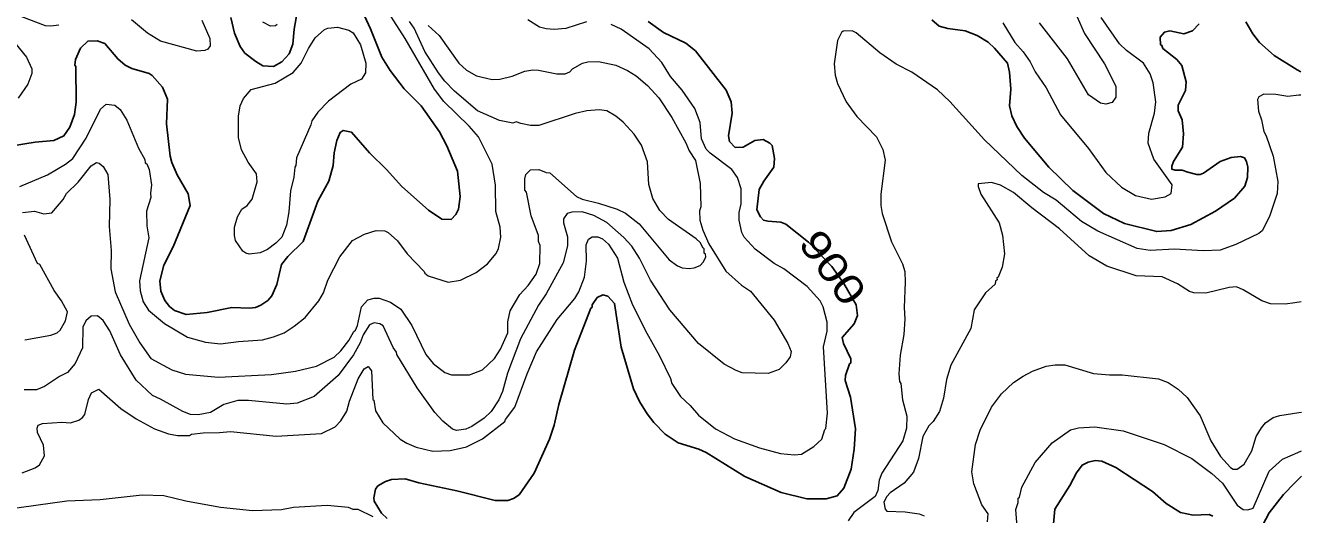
# Model space of a CAD drawing. Extents: x 447.8 to 473.9, y 7733.1 to 7760.8.
# Drawn here: x 470.364 to 473.895, y 7756.976 to 7758.328 of the extents above; entities that cross this region are included whole.
import ezdxf
from ezdxf.enums import TextEntityAlignment as Align

# ---------------------------------------------------------------- set-up
doc = ezdxf.new("R2010")
doc.units = 0
doc.header["$LTSCALE"] = 0.032
doc.layers.add('1', color=7, linetype='Continuous', lineweight=25)
doc.layers.add('2', color=7, linetype='Continuous', lineweight=13)
doc.layers.add('61', color=7, linetype='Continuous')

msp = doc.modelspace()

# ---------------------------------------------------------------- linework, layer by layer
at = {"layer": '1'}
for points in [[(471.5091, 7758.0338), (471.4587, 7758.1053), (471.4119, 7758.1529), (471.373, 7758.2035), (471.3501, 7758.2402), (471.3188, 7758.3188), (471.2785, 7758.4048)], [(471.1166, 7758.3701), (471.1071, 7758.3179), (471.1038, 7758.2762), (471.0933, 7758.2498), (471.0731, 7758.2274), (471.0504, 7758.2143), (471.0209, 7758.216), (471.0008, 7758.2279), (470.971, 7758.2515), (470.9578, 7758.2697), (470.9425, 7758.3065), (470.9321, 7758.3499)], [(472.8716, 7758.3437), (472.8917, 7758.3263), (472.9162, 7758.3198), (472.9639, 7758.3134), (472.9968, 7758.3), (473.0278, 7758.2819), (473.0455, 7758.2652), (473.0809, 7758.2235), (473.0869, 7758.1988), (473.0901, 7758.1521), (473.087, 7758.1056), (473.093, 7758.0783), (473.1068, 7758.0484), (473.1284, 7758.0164), (473.1954, 7757.9363), (473.2618, 7757.8715), (473.3469, 7757.8078), (473.4051, 7757.7802), (473.4942, 7757.758), (473.5339, 7757.7612), (473.5889, 7757.7778), (473.6567, 7757.8145), (473.7093, 7757.85), (473.7375, 7757.8833), (473.745, 7757.9071), (473.7458, 7757.9359), (473.7428, 7757.9512), (473.7367, 7757.9622), (473.7258, 7757.9655), (473.7002, 7757.963), (473.6693, 7757.9513), (473.624, 7757.9193), (473.6146, 7757.9161), (473.6048, 7757.9157), (473.5804, 7757.922), (473.5646, 7757.9279), (473.5449, 7757.9278), (473.5363, 7757.9304), (473.5355, 7757.9385), (473.5402, 7757.9512), (473.5655, 7757.9911), (473.5686, 7758.0281), (473.5646, 7758.0666), (473.5535, 7758.0918), (473.5535, 7758.1072), (473.5742, 7758.1484), (473.5759, 7758.1716), (473.5636, 7758.2175), (473.55, 7758.2335), (473.5107, 7758.2644), (473.5084, 7758.2725), (473.5047, 7758.2744), (473.5039, 7758.2952), (473.5152, 7758.3095), (473.5302, 7758.3127), (473.5691, 7758.3047), (473.5934, 7758.3128), (473.6115, 7758.3326)], [(472.4064, 7757.7898), (472.3976, 7757.7982), (472.3879, 7757.8178), (472.3944, 7757.8739), (472.4068, 7757.8975), (472.4345, 7757.9358), (472.436, 7757.9603), (472.4297, 7757.9962), (472.4237, 7758.0026), (472.4051, 7758.0128), (472.3824, 7758.0097), (472.35, 7757.9911), (472.3274, 7757.9905), (472.3119, 7758.0066), (472.3087, 7758.0222), (472.319, 7758.085), (472.3169, 7758.1169), (472.3029, 7758.1491), (472.2175, 7758.258), (472.1911, 7758.279), (472.1295, 7758.3079), (472.0865, 7758.3391)], [(473.7406, 7758.3376), (473.76, 7758.305), (473.7782, 7758.281), (473.8189, 7758.2449), (473.883, 7758.2054), (473.893, 7758.1992)], [(470.2923, 7757.9896), (470.3908, 7758.0049), (470.4425, 7758.0097), (470.4702, 7758.0224), (470.486, 7758.0469), (470.4994, 7758.0819), (470.5042, 7758.1156), (470.5026, 7758.2145), (470.5003, 7758.2177), (470.5022, 7758.2339), (470.5155, 7758.2654), (470.5364, 7758.2845), (470.5619, 7758.2854), (470.5832, 7758.2775), (470.6188, 7758.2352), (470.6393, 7758.2182), (470.6579, 7758.2088), (470.7057, 7758.1947), (470.7145, 7758.1897), (470.7431, 7758.1572), (470.7565, 7758.1242), (470.7536, 7758.0559), (470.7642, 7757.9666), (470.7685, 7757.949), (470.7833, 7757.9148), (470.8136, 7757.8622), (470.8191, 7757.8299), (470.7726, 7757.716), (470.7465, 7757.6648), (470.7352, 7757.6215), (470.7386, 7757.5931), (470.7492, 7757.5672), (470.7618, 7757.5503), (470.7759, 7757.5396), (470.808, 7757.5288), (470.8662, 7757.5343), (470.9347, 7757.5479), (470.9839, 7757.5456), (471, 7757.5481), (471.0149, 7757.5541), (471.0342, 7757.5675), (471.0453, 7757.5801), (471.0588, 7757.6118), (471.0722, 7757.6665), (471.0897, 7757.6885), (471.1318, 7757.7308), (471.1724, 7757.8422), (471.2031, 7757.8968), (471.2152, 7757.9408), (471.2176, 7757.976), (471.2252, 7758.0099), (471.2348, 7758.0321), (471.2429, 7758.0377), (471.2659, 7758.0326), (471.3154, 7757.9752), (471.3625, 7757.9298), (471.405, 7757.8824), (471.4792, 7757.8171), (471.5156, 7757.7918), (471.542, 7757.7913), (471.5547, 7757.8053)], [(471.5547, 7757.8053), (471.562, 7757.8198), (471.5663, 7757.8546), (471.559, 7757.9251), (471.5296, 7757.9949), (471.5091, 7758.0338)], [(472.5954, 7757.6613), (472.5307, 7757.7282), (472.4681, 7757.778), (472.4537, 7757.7836), (472.4182, 7757.7862), (472.4064, 7757.7898)], [(471.3648, 7756.9641), (471.3489, 7756.9792), (471.3285, 7757.012), (471.3276, 7757.022), (471.3324, 7757.0457), (471.3388, 7757.055), (471.3596, 7757.0663), (471.3767, 7757.0719), (471.4148, 7757.0742), (471.4525, 7757.0629), (471.5572, 7757.0414), (471.6637, 7757.0141), (471.6983, 7757.0141), (471.7141, 7757.0199), (471.7295, 7757.0298), (471.7717, 7757.0898), (471.814, 7757.1841), (471.8269, 7757.2229), (471.8396, 7757.2799), (471.8832, 7757.4301), (471.9286, 7757.546), (471.9317, 7757.5484), (471.9315, 7757.5552), (471.9458, 7757.5753), (471.9616, 7757.5825), (471.9755, 7757.5796), (471.9937, 7757.5594), (472.0119, 7757.4381), (472.0466, 7757.3232), (472.0627, 7757.2879), (472.0837, 7757.2537), (472.1021, 7757.2299), (472.1341, 7757.1975), (472.1696, 7757.1738), (472.2269, 7757.1563), (472.2473, 7757.1474), (472.3541, 7757.0808), (472.455, 7757.0359), (472.5262, 7757.0189), (472.5791, 7757.019), (472.6101, 7757.0267), (472.6284, 7757.0479), (472.6485, 7757.1011), (472.6572, 7757.1565), (472.6605, 7757.2126), (472.647, 7757.3004), (472.6317, 7757.3463), (472.6329, 7757.3596), (472.6443, 7757.3921), (472.6476, 7757.3945), (472.6476, 7757.4058), (472.6274, 7757.4488), (472.6238, 7757.4649), (472.657, 7757.5029), (472.666, 7757.5261), (472.6622, 7757.5549), (472.6286, 7757.6144), (472.5954, 7757.6613)], [(473.6491, 7756.9711), (473.6397, 7756.9756), (473.5953, 7756.9734), (473.5599, 7756.9812), (473.5205, 7757.0056), (473.4825, 7757.039), (473.381, 7757.1057), (473.3423, 7757.1226), (473.3242, 7757.1247), (473.3046, 7757.1198), (473.2875, 7757.1119), (473.272, 7757.0908), (473.2538, 7757.0561), (473.2119, 7756.9898), (473.2089, 7756.9497)], [(473.8947, 7757.0816), (473.8766, 7757.0631), (473.845, 7757.0307), (473.8051, 7756.9804), (473.7684, 7756.9103)]]:
    msp.add_lwpolyline(points, dxfattribs=at)
at = {"layer": '2'}
msp.add_line((473.8878, 7757.2579), (473.8944, 7757.2589), dxfattribs=at)
for points in [[(471.3017, 7757.7511), (471.3343, 7757.7611), (471.3577, 7757.7595), (471.3677, 7757.7554), (471.393, 7757.7318), (471.4197, 7757.696), (471.4665, 7757.6478), (471.4684, 7757.643), (471.4784, 7757.6356), (471.5332, 7757.6178), (471.5671, 7757.6233), (471.611, 7757.6443), (471.6419, 7757.6685), (471.6659, 7757.6974), (471.6729, 7757.7115), (471.6793, 7757.742), (471.677, 7757.7705), (471.665, 7757.8138), (471.6641, 7757.8862), (471.6553, 7757.9439), (471.6171, 7758.02), (471.5917, 7758.0492), (471.5218, 7758.1179), (471.4955, 7758.1518), (471.4147, 7758.2921), (471.3431, 7758.4033)], [(470.4558, 7758.3287), (470.4341, 7758.3256), (470.419, 7758.3272), (470.3532, 7758.3515)], [(470.8519, 7758.3425), (470.8742, 7758.2913), (470.8744, 7758.2711), (470.8681, 7758.2625), (470.8601, 7758.2583), (470.8378, 7758.2566), (470.7374, 7758.2844), (470.7016, 7758.3067), (470.6568, 7758.3438)], [(471.9159, 7758.3382), (471.8594, 7758.3197), (471.8265, 7758.3168), (471.8041, 7758.3184), (471.7865, 7758.3231), (471.7536, 7758.3432)], [(473.0679, 7758.3349), (473.1015, 7758.2804), (473.1244, 7758.2545), (473.1435, 7758.2271), (473.158, 7758.1997), (473.1883, 7758.155), (473.2278, 7758.0805), (473.3055, 7757.9875), (473.3533, 7757.9213), (473.3965, 7757.8811), (473.4353, 7757.8573), (473.4794, 7757.8478), (473.5178, 7757.8539), (473.5341, 7757.8633), (473.5373, 7757.8869), (473.4865, 7757.9578), (473.4703, 7758.0026), (473.4722, 7758.0302), (473.4877, 7758.0854), (473.4917, 7758.1168), (473.4844, 7758.1691), (473.4759, 7758.1937), (473.4577, 7758.2231), (473.4102, 7758.2587), (473.3913, 7758.2769), (473.3407, 7758.3502)], [(473.2727, 7758.3534), (473.2942, 7758.3053), (473.3492, 7758.2218), (473.3811, 7758.1596), (473.381, 7758.1292), (473.3711, 7758.1152), (473.3535, 7758.11), (473.3385, 7758.1125), (473.3049, 7758.1358), (473.2476, 7758.2351), (473.1693, 7758.3354)], [(471.0601, 7758.3308), (471.0552, 7758.327), (471.0416, 7758.326), (471.0204, 7758.3373)], [(472.2308, 7757.7275), (472.2194, 7757.7382), (472.1432, 7757.7915), (472.119, 7757.8163), (472.1, 7757.8497), (472.0883, 7757.8877), (472.0848, 7757.9507), (472.0681, 7757.997), (472.0478, 7758.0276), (472.0179, 7758.06), (471.9971, 7758.0768), (471.9724, 7758.0914), (471.9512, 7758.0946), (471.9175, 7758.0913), (471.8845, 7758.0842), (471.784, 7758.0514), (471.7608, 7758.0514), (471.7345, 7758.0564), (471.7218, 7758.0617), (471.7119, 7758.0579), (471.6751, 7758.0646), (471.6146, 7758.0919), (471.5509, 7758.1462), (471.5244, 7758.1735), (471.5064, 7758.197), (471.4692, 7758.256), (471.439, 7758.3201), (471.4266, 7758.3386)], [(471.478, 7758.3277), (471.5084, 7758.3001), (471.5629, 7758.2232), (471.5841, 7758.2041), (471.612, 7758.1889), (471.655, 7758.1781), (471.6766, 7758.1795), (471.7108, 7758.1874), (471.7455, 7758.2013), (471.7675, 7758.2052), (471.7833, 7758.2044), (471.8341, 7758.1941), (471.857, 7758.1941), (471.8702, 7758.1992), (471.8771, 7758.2076), (471.9053, 7758.2239), (471.92, 7758.2271), (471.9493, 7758.2278), (471.9971, 7758.218), (472.0298, 7758.2032), (472.0532, 7758.1882), (472.0847, 7758.1622), (472.1167, 7758.1277), (472.1525, 7758.0732), (472.1906, 7758.0036), (472.2002, 7757.9811), (472.2177, 7757.9541), (472.2308, 7757.891), (472.2325, 7757.8263), (472.2292, 7757.8152), (472.2301, 7757.7897), (472.2378, 7757.7613), (472.2543, 7757.7238), (472.3018, 7757.6485)], [(471.922, 7757.7366), (471.9317, 7757.7434), (471.9471, 7757.7435), (471.9604, 7757.738), (471.9774, 7757.7228), (472.0017, 7757.6839), (472.0199, 7757.6182), (472.0434, 7757.5557), (472.0827, 7757.4772), (472.1182, 7757.4143), (472.1487, 7757.3515), (472.1527, 7757.3373), (472.1763, 7757.3021), (472.2034, 7757.2765), (472.2258, 7757.2501), (472.273, 7757.2121), (472.3257, 7757.1847), (472.3952, 7757.1598), (472.453, 7757.1442), (472.4914, 7757.1408), (472.5114, 7757.1424), (472.5453, 7757.1636), (472.5673, 7757.184), (472.5756, 7757.211), (472.5787, 7757.2133), (472.5835, 7757.2559), (472.5723, 7757.4392), (472.5819, 7757.4822), (472.5819, 7757.507), (472.5707, 7757.5501), (472.5624, 7757.5665), (472.5266, 7757.6057), (472.462, 7757.6544), (472.4357, 7757.67), (472.3826, 7757.7089), (472.3525, 7757.7424), (472.346, 7757.7555), (472.3383, 7757.7891), (472.3383, 7757.8106), (472.3446, 7757.8349), (472.3438, 7757.8761), (472.3342, 7757.9071), (472.3182, 7757.9295), (472.2584, 7757.9743), (472.2474, 7757.9859), (472.2341, 7758.0143), (472.2308, 7758.0591), (472.2164, 7758.0979), (472.1813, 7758.1489), (472.149, 7758.1865), (472.1247, 7758.2255), (472.0892, 7758.2636), (472.0122, 7758.3179), (471.9847, 7758.3301)], [(473.8931, 7758.1354), (473.8878, 7758.1348), (473.8573, 7758.1316), (473.8237, 7758.1372), (473.7908, 7758.1379), (473.7766, 7758.1308), (473.7732, 7758.1232), (473.7762, 7758.0905), (473.7844, 7758.0671), (473.7906, 7758.0344), (473.7971, 7758.0223), (473.8164, 7757.9661), (473.8293, 7757.8964), (473.8276, 7757.8633), (473.8066, 7757.7997), (473.7861, 7757.76), (473.7768, 7757.7523), (473.7132, 7757.7221), (473.6696, 7757.7069), (473.6229, 7757.7044), (473.5432, 7757.7091), (473.4762, 7757.7052), (473.4396, 7757.7111), (473.3307, 7757.7588), (473.2859, 7757.7857), (473.2155, 7757.8443), (473.1805, 7757.8658), (473.1208, 7757.9129), (473.0172, 7758.0113), (472.9216, 7758.1174), (472.8871, 7758.1502), (472.8162, 7758.1984), (472.7734, 7758.2211), (472.7276, 7758.2519), (472.6623, 7758.3075), (472.651, 7758.3133), (472.6263, 7758.3124), (472.6218, 7758.3084), (472.6106, 7758.286), (472.6012, 7758.222), (472.6041, 7758.1904), (472.6106, 7758.1675), (472.6344, 7758.117), (472.6643, 7758.0757), (472.7188, 7758.0196), (472.7362, 7757.9845), (472.7423, 7757.9557), (472.7311, 7757.8613), (472.7311, 7757.8298), (472.7342, 7757.8081), (472.7599, 7757.7291), (472.7907, 7757.6687), (472.7967, 7757.6474), (472.7983, 7757.6176), (472.7952, 7757.5476), (472.7975, 7757.5153), (472.7944, 7757.4733), (472.784, 7757.4165), (472.7807, 7757.3641), (472.7824, 7757.3432), (472.7863, 7757.3379), (472.7904, 7757.2928), (472.8024, 7757.2475), (472.8014, 7757.2138), (472.7918, 7757.1791), (472.7337, 7757.0901), (472.7263, 7757.0702), (472.7222, 7757.0415), (472.7151, 7757.0249), (472.6561, 7756.9809), (472.6399, 7756.9579)], [(470.3256, 7758.29), (470.3667, 7758.2399), (470.3808, 7758.2082), (470.3808, 7758.1951), (470.3698, 7758.1659), (470.3435, 7758.1264)], [(470.3482, 7757.8826), (470.4242, 7757.9151), (470.4748, 7757.9441), (470.4948, 7757.9603), (470.5317, 7758.0164), (470.5716, 7758.0963), (470.5868, 7758.1101), (470.6105, 7758.1075), (470.626, 7758.0954), (470.6439, 7758.0655), (470.6768, 7757.9883), (470.6936, 7757.9569), (470.6952, 7757.948), (470.6997, 7757.9453), (470.7062, 7757.9292), (470.7126, 7757.8868), (470.7095, 7757.8642), (470.7109, 7757.8525), (470.6983, 7757.8146), (470.6999, 7757.7741), (470.7046, 7757.7403), (470.679, 7757.6212), (470.6806, 7757.5942), (470.6891, 7757.564), (470.7041, 7757.5405), (470.7481, 7757.5036), (470.8123, 7757.4661), (470.8619, 7757.4523), (470.903, 7757.4471), (470.9535, 7757.4543), (471.0194, 7757.4588), (471.05, 7757.4664), (471.0797, 7757.4783), (471.1076, 7757.4963), (471.1372, 7757.5205), (471.1753, 7757.5659)], [(470.3553, 7757.8108), (470.3888, 7757.8141), (470.4145, 7757.807), (470.4368, 7757.8094), (470.4681, 7757.8467), (470.4774, 7757.863), (470.5091, 7757.8944), (470.545, 7757.9395), (470.5604, 7757.9486), (470.5678, 7757.9469), (470.5787, 7757.9375), (470.5915, 7757.9154), (470.5972, 7757.8468), (470.5949, 7757.7721), (470.6004, 7757.7058), (470.5997, 7757.6551), (470.6118, 7757.5909), (470.6502, 7757.5016), (470.6799, 7757.4499), (470.7102, 7757.4072), (470.7688, 7757.3751), (470.8069, 7757.3637), (470.8975, 7757.3549), (471.0449, 7757.3629), (471.1107, 7757.3722), (471.1687, 7757.3857), (471.2181, 7757.4108), (471.2367, 7757.4285), (471.2584, 7757.4565), (471.272, 7757.4818), (471.2768, 7757.4848), (471.2825, 7757.4984), (471.2931, 7757.5494), (471.3106, 7757.569), (471.3287, 7757.5737), (471.3427, 7757.5736), (471.3741, 7757.5627), (471.402, 7757.5431), (471.4324, 7757.4983), (471.4714, 7757.4176), (471.4918, 7757.3933), (471.5238, 7757.3681), (471.5428, 7757.3613), (471.5922, 7757.3621), (471.6283, 7757.3754), (471.6615, 7757.4073), (471.6779, 7757.4328), (471.6986, 7757.4777), (471.6987, 7757.5082), (471.7046, 7757.539), (471.7313, 7757.5837), (471.7544, 7757.6087), (471.7767, 7757.6403), (471.7867, 7757.6698), (471.7876, 7757.7197), (471.7836, 7757.7308), (471.7835, 7757.7468), (471.7631, 7757.8018), (471.7498, 7757.8672), (471.7451, 7757.8722), (471.7451, 7757.9036), (471.7486, 7757.9154), (471.7611, 7757.9289), (471.7842, 7757.9294), (471.8043, 7757.9215), (471.8148, 7757.9205), (471.8882, 7757.8549), (471.9044, 7757.8471), (471.9498, 7757.8362), (472.0011, 7757.8196), (472.0237, 7757.8087), (472.0619, 7757.7794), (472.1445, 7757.6801), (472.1678, 7757.663), (472.1813, 7757.6579), (472.2001, 7757.6554), (472.2139, 7757.6572), (472.2308, 7757.6637), (472.2401, 7757.6743), (472.246, 7757.6878)], [(473.894, 7757.5634), (473.8766, 7757.5609), (473.8491, 7757.5569), (473.8087, 7757.558), (473.7846, 7757.5663), (473.733, 7757.5968), (473.7145, 7757.6049), (473.6945, 7757.6033), (473.6301, 7757.5873), (473.5972, 7757.5881), (473.5845, 7757.5926), (473.5512, 7757.6133), (473.5093, 7757.6323), (473.4376, 7757.6359), (473.3559, 7757.662), (473.3068, 7757.6905), (473.2254, 7757.7655), (473.1488, 7757.8234), (473.0979, 7757.8658), (473.0616, 7757.8861), (473.0368, 7757.8939), (473.0004, 7757.8899), (473.0004, 7757.8826), (473.0078, 7757.8617), (473.0579, 7757.7823), (473.0678, 7757.7481), (473.0726, 7757.696), (473.0665, 7757.6597), (473.0549, 7757.6316), (473.0518, 7757.6296), (473.0523, 7757.6244), (473.0484, 7757.6206), (473.0468, 7757.6125), (473.0207, 7757.588), (472.9892, 7757.5412), (472.9794, 7757.4899), (472.9245, 7757.3883), (472.9121, 7757.3485), (472.9041, 7757.2976), (472.8932, 7757.2601), (472.8758, 7757.2328), (472.8637, 7757.2203), (472.8472, 7757.1911), (472.8349, 7757.1299), (472.8208, 7757.0928), (472.7952, 7757.0623), (472.7565, 7757.0356), (472.7469, 7757.0251), (472.7391, 7757.0098), (472.7428, 7756.9907), (472.7471, 7756.9846), (472.798, 7756.9829), (472.8368, 7756.9772), (472.8509, 7756.9717)], [(472.4824, 7757.4262), (472.4793, 7757.4119), (472.4679, 7757.3947), (472.4494, 7757.3769), (472.4189, 7757.3651), (472.3465, 7757.3676), (472.33, 7757.3734), (472.2971, 7757.391), (472.2259, 7757.4486), (472.1472, 7757.541), (472.0936, 7757.6233), (472.0625, 7757.6842), (472.0418, 7757.7176), (472.0199, 7757.7412), (471.9722, 7757.7826), (471.9369, 7757.802), (471.9045, 7757.8124), (471.8756, 7757.8118), (471.8622, 7757.8076), (471.8527, 7757.7927), (471.8526, 7757.7816), (471.8637, 7757.7435), (471.8638, 7757.7184), (471.8518, 7757.6717), (471.8048, 7757.5858), (471.7829, 7757.5539), (471.7335, 7757.4608), (471.6976, 7757.3667), (471.6833, 7757.3155), (471.6736, 7757.2928), (471.6526, 7757.26), (471.6331, 7757.2421), (471.599, 7757.2189), (471.5825, 7757.2111), (471.5567, 7757.2081), (471.5449, 7757.2115), (471.5188, 7757.2332), (471.4967, 7757.2574), (471.4474, 7757.3258), (471.391, 7757.4179), (471.3907, 7757.4242), (471.3811, 7757.4373), (471.3538, 7757.4974), (471.3439, 7757.5027), (471.3282, 7757.5055), (471.3157, 7757.5), (471.2983, 7757.472), (471.2897, 7757.45), (471.2717, 7757.4171), (471.2287, 7757.3596), (471.1628, 7757.3018), (471.1157, 7757.2836), (471.0869, 7757.2803), (470.9806, 7757.2906), (470.9515, 7757.2906), (470.9128, 7757.2793), (470.8755, 7757.2576), (470.8414, 7757.2507), (470.8204, 7757.2522), (470.7987, 7757.2605), (470.7375, 7757.2947), (470.715, 7757.3042), (470.6697, 7757.3466), (470.6267, 7757.4168), (470.5972, 7757.4838), (470.5786, 7757.5118), (470.563, 7757.5253), (470.5453, 7757.5238), (470.5303, 7757.5106), (470.5221, 7757.4938), (470.5216, 7757.4367), (470.5012, 7757.3928), (470.4798, 7757.3684), (470.458, 7757.3574), (470.4163, 7757.3293), (470.3937, 7757.3204), (470.3596, 7757.3204)], [(470.3618, 7757.4582), (470.4339, 7757.4715), (470.451, 7757.4774), (470.4599, 7757.4854), (470.4742, 7757.5107), (470.4799, 7757.5358), (470.4637, 7757.5663), (470.4432, 7757.5948), (470.4031, 7757.6665), (470.3972, 7757.6697), (470.3609, 7757.7481)], [(471.1753, 7757.5659), (471.1882, 7757.5887), (471.2001, 7757.6235), (471.2333, 7757.6884), (471.2682, 7757.7331), (471.3017, 7757.7511)], [(471.8842, 7757.5727), (471.895, 7757.5915), (471.9102, 7757.6316), (471.9166, 7757.6759), (471.9151, 7757.7208), (471.922, 7757.7366)], [(472.246, 7757.6878), (472.2454, 7757.6955), (472.2421, 7757.6983), (472.2419, 7757.7105), (472.2389, 7757.7118), (472.2308, 7757.7275)], [(472.3018, 7757.6485), (472.3448, 7757.6094), (472.3696, 7757.5927), (472.4356, 7757.5125), (472.4732, 7757.448), (472.4824, 7757.4262)], [(470.3544, 7757.0909), (470.3907, 7757.1049), (470.4029, 7757.1126), (470.4167, 7757.1376), (470.4132, 7757.1669), (470.397, 7757.2026), (470.3961, 7757.2142), (470.3992, 7757.2223), (470.4108, 7757.2274), (470.4638, 7757.2306), (470.4885, 7757.2291), (470.5112, 7757.236), (470.5219, 7757.2435), (470.5278, 7757.2522), (470.5381, 7757.2934), (470.5461, 7757.3122), (470.5664, 7757.3225), (470.6279, 7757.2687), (470.67, 7757.2397), (470.7209, 7757.2128), (470.7598, 7757.1984), (470.7845, 7757.1938), (470.8176, 7757.1937), (470.8231, 7757.1978), (470.855, 7757.2017), (470.9006, 7757.2018), (470.9313, 7757.205), (471.0578, 7757.1921), (471.1832, 7757.1993), (471.2208, 7757.2178), (471.2364, 7757.2348), (471.2529, 7757.261), (471.26, 7757.2885), (471.2841, 7757.3508), (471.301, 7757.3786), (471.3124, 7757.3849), (471.3216, 7757.3727), (471.3251, 7757.2934), (471.3275, 7757.2916), (471.3324, 7757.2624), (471.3526, 7757.2287), (471.4009, 7757.1841), (471.4189, 7757.1723), (471.4446, 7757.1616), (471.4906, 7757.1506), (471.5388, 7757.1527), (471.5841, 7757.1622), (471.6282, 7757.1844), (471.6904, 7757.233), (471.6916, 7757.2379), (471.7179, 7757.2726), (471.7518, 7757.3643), (471.7777, 7757.4256), (471.8353, 7757.5149), (471.8842, 7757.5727)], [(473.0261, 7756.9556), (473.0276, 7756.9769), (473.0103, 7757.0023), (472.9884, 7757.0603), (472.9828, 7757.0932), (472.9923, 7757.1693), (473.0053, 7757.2084), (473.0366, 7757.2725), (473.0643, 7757.3089), (473.0979, 7757.3401), (473.1241, 7757.3582), (473.1501, 7757.3719), (473.1883, 7757.3853), (473.2129, 7757.3892), (473.2396, 7757.3892), (473.3191, 7757.3653), (473.3631, 7757.3613), (473.3983, 7757.362), (473.4986, 7757.3509), (473.5259, 7757.3405), (473.5532, 7757.3221), (473.5788, 7757.2989), (473.6143, 7757.2482), (473.6441, 7757.1793), (473.6704, 7757.1361), (473.6979, 7757.1053), (473.7061, 7757.1008), (473.717, 7757.1009), (473.7364, 7757.1147), (473.7569, 7757.1517), (473.7694, 7757.1912), (473.7839, 7757.2155), (473.7954, 7757.2288), (473.8164, 7757.2434), (473.8344, 7757.2495), (473.8878, 7757.2579)], [(473.1213, 7757.0507), (473.1579, 7757.1189), (473.2045, 7757.1734), (473.2555, 7757.2097), (473.2777, 7757.2153), (473.3226, 7757.2177)], [(473.3226, 7757.2177), (473.4008, 7757.2066), (473.5151, 7757.1688), (473.5913, 7757.1299), (473.647, 7757.089), (473.6763, 7757.062), (473.7167, 7757.0016), (473.7335, 7756.9892), (473.7462, 7756.9885), (473.7609, 7756.9928), (473.8052, 7757.095), (473.8425, 7757.1287), (473.8846, 7757.1473), (473.8946, 7757.1517)], [(473.1078, 7756.9415), (473.1046, 7756.9891), (473.1109, 7757.0086), (473.111, 7757.021), (473.1141, 7757.0238), (473.1213, 7757.0507)], [(471.326, 7756.9688), (471.2842, 7756.9892), (471.2706, 7756.9891), (471.2577, 7756.9949), (471.1981, 7757.0005), (471.1054, 7756.9949), (471.0724, 7756.9885), (470.9923, 7756.9853), (470.9031, 7756.995), (470.8078, 7757.0126), (470.7467, 7757.0271), (470.6867, 7757.0286), (470.5703, 7757.0159), (470.4779, 7757.0125), (470.3067, 7756.9884), (470.2723, 7756.9786), (470.1825, 7756.9693)]]:
    msp.add_lwpolyline(points, dxfattribs=at)
msp.add_lwpolyline([(470.9532, 7758.0181), (470.9532, 7758.0774), (470.9581, 7758.1055), (470.9669, 7758.1254), (470.9883, 7758.1505), (471.0548, 7758.1687), (471.1041, 7758.1975), (471.1269, 7758.2234), (471.147, 7758.2644), (471.165, 7758.2937), (471.191, 7758.3162), (471.2008, 7758.3202), (471.2272, 7758.3231), (471.2587, 7758.3146), (471.2704, 7758.307), (471.2905, 7758.2745), (471.3058, 7758.2233), (471.3045, 7758.1964), (471.2934, 7758.1792), (471.2644, 7758.1654), (471.2018, 7758.1183), (471.1724, 7758.0881), (471.1557, 7758.0638), (471.1534, 7758.0528), (471.1132, 7757.9621), (471.1118, 7757.9405), (471.1087, 7757.9363), (471.1061, 7757.9081), (471.0975, 7757.8705), (471.0926, 7757.8122), (471.0861, 7757.776), (471.0729, 7757.7425), (471.0565, 7757.7259), (471.0332, 7757.7085), (471.0131, 7757.6989), (470.9831, 7757.6955), (470.9737, 7757.698), (470.9654, 7757.7041), (470.9452, 7757.7335), (470.942, 7757.7468), (470.942, 7757.7698), (470.9503, 7757.7986), (470.9622, 7757.8198), (470.9771, 7757.8295), (470.9906, 7757.8475), (471.0045, 7757.8953), (471.003, 7757.9176), (470.9797, 7757.9501), (470.9613, 7757.9838)], close=True, dxfattribs=at)

# ---------------------------------------------------------------- texts
at = {"layer": '61', "width": 1.25}
msp.add_text('900', height=0.08, rotation=306.037, dxfattribs=at).set_placement((472.5652, 7757.6348), align=Align.CENTER)

doc.saveas('drawing.dxf')
